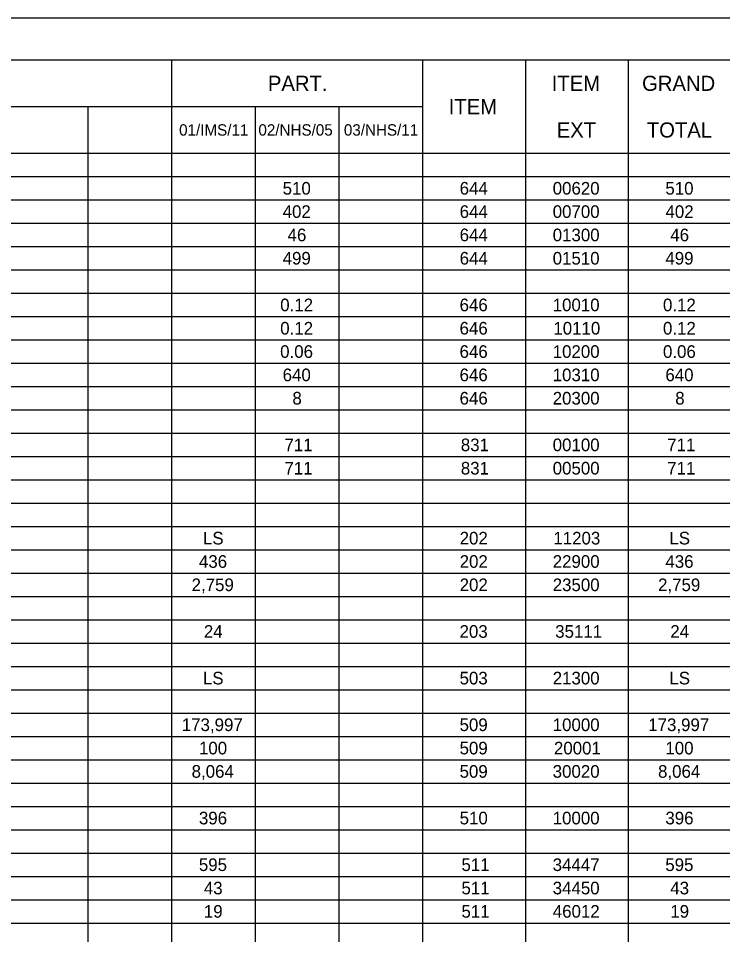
# Model space of a CAD drawing. Extents: x 0 to 34, y 0 to 22.
# Drawn here: x 8.7 to 17.16, y 11 to 22 of the extents above; entities that cross this region are included whole.
import ezdxf

# ---------------------------------------------------------------- set-up
doc = ezdxf.new("R2010")
doc.units = 0
for name, color, linetype in [('SH_Border', 7, 'Continuous'), ('SH_Cut_Line', 7, 'Continuous'), ('SH_Text', 7, 'Continuous')]:
    doc.layers.add(name, color=color, linetype=linetype)

msp = doc.modelspace()

# ---------------------------------------------------------------- linework, layer by layer
at = {"layer": 'SH_Border'}
msp.add_lwpolyline([(1.5, 21.5), (33.5, 21.5), (33.5, 0.5), (1.5, 0.5)], close=True, dxfattribs=at)
at = {"layer": 'SH_Cut_Line'}
msp.add_lwpolyline([(0, 0), (34, 0), (34, 22), (0, 22)], close=True, dxfattribs=at)
at = {"layer": 'SH_Text'}
for p, q in [((1.5, 21.5), (32.004, 21.5)), ((10.542, 21.5), (10.542, 0.5)), ((13.556, 21.5), (13.556, 0.5)), ((14.792, 21.5), (14.792, 0.5)), ((16.027, 21.5), (16.027, 0.5)), ((1.5, 20.94), (13.556, 20.94)), ((9.538, 20.94), (9.538, 0.5)), ((11.547, 20.94), (11.547, 0.5)), ((12.552, 20.94), (12.552, 0.5)), ((1.5, 20.38), (32.004, 20.38)), ((1.5, 20.1), (32.004, 20.1)), ((1.5, 19.82), (32.004, 19.82)), ((1.5, 19.54), (32.004, 19.54)), ((1.5, 19.26), (32.004, 19.26)), ((1.5, 18.98), (32.004, 18.98)), ((1.5, 18.7), (32.004, 18.7)), ((1.5, 18.42), (32.004, 18.42)), ((1.5, 18.14), (32.004, 18.14)), ((1.5, 17.86), (32.004, 17.86)), ((1.5, 17.58), (32.004, 17.58)), ((1.5, 17.3), (32.004, 17.3)), ((1.5, 17.02), (32.004, 17.02)), ((1.5, 16.74), (32.004, 16.74)), ((1.5, 16.46), (32.004, 16.46)), ((1.5, 16.18), (32.004, 16.18)), ((1.5, 15.9), (32.004, 15.9)), ((1.5, 15.62), (32.004, 15.62)), ((1.5, 15.34), (32.004, 15.34)), ((1.5, 15.06), (32.004, 15.06)), ((1.5, 14.78), (32.004, 14.78)), ((1.5, 14.5), (32.004, 14.5)), ((1.5, 14.22), (32.004, 14.22)), ((1.5, 13.94), (32.004, 13.94)), ((1.5, 13.66), (32.004, 13.66)), ((1.5, 13.38), (32.004, 13.38)), ((1.5, 13.1), (32.004, 13.1)), ((1.5, 12.82), (32.004, 12.82)), ((1.5, 12.54), (32.004, 12.54)), ((1.5, 12.26), (32.004, 12.26)), ((1.5, 11.98), (32.004, 11.98)), ((1.5, 11.7), (32.004, 11.7)), ((1.5, 11.42), (32.004, 11.42)), ((1.5, 11.14), (32.004, 11.14))]:
    msp.add_line(p, q, dxfattribs=at)

# ---------------------------------------------------------------- texts
for s, height, p in [('PART.', 0.1818, (11.701, 21.129)), ('ITEM', 0.1818, (15.108, 21.129)), ('GRAND', 0.1818, (16.193, 21.129)), ('ITEM', 0.1818, (13.872, 20.849)), ('01/IMS/11', 0.1364, (10.635, 20.592)), ('02/NHS/05', 0.1364, (11.587, 20.592)), ('03/NHS/11', 0.1364, (12.613, 20.592)), ('EXT', 0.1818, (15.168, 20.569)), ('TOTAL', 0.1818, (16.25, 20.569)), ('510', 0.1515, (11.878, 19.884)), ('644', 0.1515, (14.003, 19.884)), ('00620', 0.1515, (15.12, 19.884)), ('510', 0.1515, (16.473, 19.884)), ('402', 0.1515, (11.878, 19.604)), ('644', 0.1515, (14.003, 19.604)), ('00700', 0.1515, (15.12, 19.604)), ('402', 0.1515, (16.474, 19.604)), ('46', 0.1515, (11.937, 19.324)), ('644', 0.1515, (14.003, 19.324)), ('01300', 0.1515, (15.12, 19.324)), ('46', 0.1515, (16.532, 19.324)), ('499', 0.1515, (11.878, 19.044)), ('644', 0.1515, (14.003, 19.044)), ('01510', 0.1515, (15.12, 19.044)), ('499', 0.1515, (16.473, 19.044)), ('0.12', 0.1515, (11.849, 18.484)), ('646', 0.1515, (14.002, 18.484)), ('10010', 0.1515, (15.12, 18.484)), ('0.12', 0.1515, (16.444, 18.484)), ('0.12', 0.1515, (11.849, 18.204)), ('646', 0.1515, (14.002, 18.204)), ('10110', 0.1515, (15.128, 18.204)), ('0.12', 0.1515, (16.444, 18.204)), ('0.06', 0.1515, (11.848, 17.924)), ('646', 0.1515, (14.002, 17.924)), ('10200', 0.1515, (15.12, 17.924)), ('0.06', 0.1515, (16.444, 17.924)), ('640', 0.1515, (11.878, 17.644)), ('646', 0.1515, (14.002, 17.644)), ('10310', 0.1515, (15.12, 17.644)), ('640', 0.1515, (16.473, 17.644)), ('8', 0.152, (11.995, 17.364)), ('646', 0.1515, (14.002, 17.364)), ('20300', 0.1515, (15.12, 17.364)), ('8', 0.152, (16.591, 17.364)), ('711', 0.1515, (11.9, 16.804)), ('831', 0.1515, (14.017, 16.804)), ('00100', 0.1515, (15.12, 16.804)), ('711', 0.1515, (16.495, 16.804)), ('711', 0.1515, (11.9, 16.524)), ('831', 0.1515, (14.017, 16.524)), ('00500', 0.1515, (15.12, 16.524)), ('711', 0.1515, (16.495, 16.524)), ('LS', 0.1515, (10.921, 15.684)), ('202', 0.1515, (14.003, 15.684)), ('11203', 0.1515, (15.128, 15.684)), ('LS', 0.1515, (16.521, 15.684)), ('436', 0.1515, (10.873, 15.404)), ('202', 0.1515, (14.003, 15.404)), ('22900', 0.1515, (15.12, 15.404)), ('436', 0.1515, (16.473, 15.404)), ('2,759', 0.1515, (10.785, 15.124)), ('202', 0.1515, (14.003, 15.124)), ('23500', 0.1515, (15.12, 15.124)), ('2,759', 0.1515, (16.385, 15.124)), ('24', 0.1515, (10.932, 14.564)), ('203', 0.1515, (14.002, 14.564)), ('35111', 0.1515, (15.15, 14.564)), ('24', 0.1515, (16.532, 14.564)), ('LS', 0.1515, (10.921, 14.004)), ('503', 0.1515, (14.002, 14.004)), ('21300', 0.1515, (15.12, 14.004)), ('LS', 0.1515, (16.521, 14.004)), ('173,997', 0.1515, (10.667, 13.444)), ('509', 0.1515, (14.002, 13.444)), ('10000', 0.1515, (15.12, 13.444)), ('173,997', 0.1515, (16.267, 13.444)), ('100', 0.1515, (10.873, 13.164)), ('509', 0.1515, (14.002, 13.164)), ('20001', 0.1515, (15.135, 13.164)), ('100', 0.1515, (16.473, 13.164)), ('8,064', 0.1515, (10.785, 12.884)), ('509', 0.1515, (14.002, 12.884)), ('30020', 0.1515, (15.12, 12.884)), ('8,064', 0.1515, (16.385, 12.884)), ('396', 0.1515, (10.873, 12.324)), ('510', 0.1515, (14.003, 12.324)), ('10000', 0.1515, (15.12, 12.324)), ('396', 0.1515, (16.473, 12.324)), ('595', 0.1515, (10.872, 11.764)), ('511', 0.1515, (14.025, 11.764)), ('34447', 0.1515, (15.12, 11.764)), ('595', 0.1515, (16.472, 11.764)), ('43', 0.1515, (10.932, 11.484)), ('511', 0.1515, (14.025, 11.484)), ('34450', 0.1515, (15.12, 11.484)), ('43', 0.1515, (16.532, 11.484)), ('19', 0.1515, (10.932, 11.204)), ('511', 0.1515, (14.025, 11.204)), ('46012', 0.1515, (15.121, 11.204)), ('19', 0.1515, (16.532, 11.204))]:
    msp.add_text(s, height=height, dxfattribs=at).set_placement(p)

doc.saveas('drawing.dxf')
